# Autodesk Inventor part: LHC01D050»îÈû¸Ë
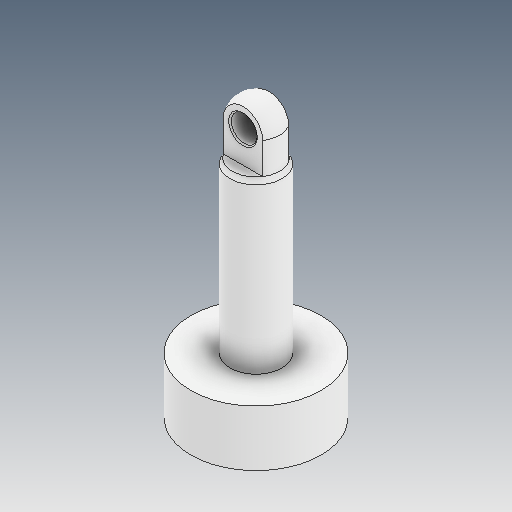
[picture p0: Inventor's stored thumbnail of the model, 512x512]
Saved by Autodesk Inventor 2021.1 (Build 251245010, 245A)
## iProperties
Created: 2021-06
Part Number: LHC01D050»îÈû¸Ë
Material: Ogólny
Document SubType Name: Modeling
Designer: user
Density: 1 g/cm^3
Appearance: Domyślna
Author: user
Revision Number: ÈÎºÎ
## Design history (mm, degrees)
feature "ÊäÈë1"
node "Bryła1"
